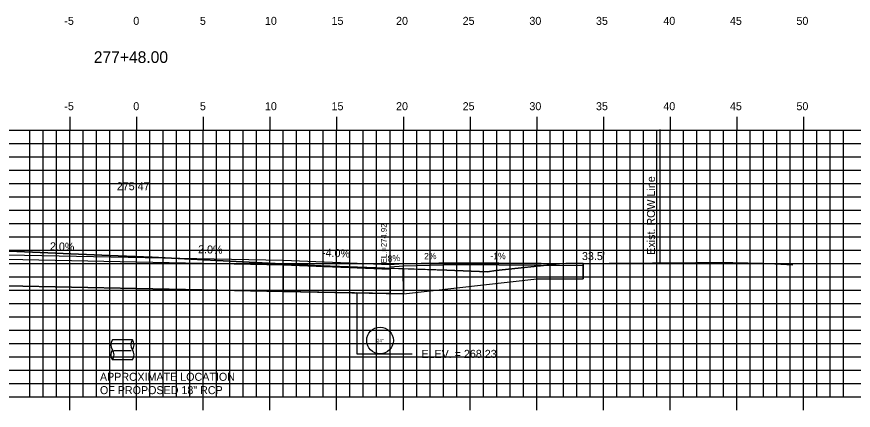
# Model space of a CAD drawing. Extents: x 854231 to 854401, y 366268 to 366378.
# Drawn here: x 854304.8 to 854367.5, y 366306.2 to 366335.7 of the extents above; entities that cross this region are included whole.
import ezdxf

# ---------------------------------------------------------------- set-up
doc = ezdxf.new("R2010")
doc.units = 0
for name, color, linetype in [('ANNOTATION', 7, 'Continuous'), ('D_Drainage_Culvert', 7, 'Continuous'), ('D_Drainage_Text', 7, 'Continuous'), ('D_Roadway_Centerline_Text', 7, 'Continuous'), ('D_Roadway_Drive_Gravel_RT', 7, 'Continuous'), ('D_Roadway_Drive_SubGrade', 7, 'Continuous'), ('D_Roadway_Edge_TW', 7, 'Continuous'), ('D_Roadway_SubGrade', 7, 'Continuous'), ('D_Text_Standard', 7, 'Continuous'), ('E_ROW_Line', 7, 'Continuous'), ('H_V ANNOTATION', 7, 'Continuous'), ('JUNK COM EXC', 7, 'Continuous'), ('junk strct exc', 7, 'Continuous'), ('MAJOR', 7, 'Continuous'), ('MINOR', 7, 'Continuous'), ('PDRAIN', 7, 'Continuous'), ('S_Roadway_Centerline', 7, 'Continuous')]:
    doc.layers.add(name, color=color, linetype=linetype)

msp = doc.modelspace()

# ---------------------------------------------------------------- linework, layer by layer
at = {"layer": 'ANNOTATION'}
msp.add_line((854312.071, 366310.722), (854313.382, 366310.722), dxfattribs=at)
at = {"layer": 'D_Drainage_Culvert'}
for p, q in [((854313.461, 366311.514), (854311.961, 366311.514)), ((854313.461, 366310.014), (854311.961, 366310.014))]:
    msp.add_line(p, q, dxfattribs=at)
for centre, start, end in [((854312.461, 366311.139), 143.1301, 216.8699), ((854313.961, 366311.139), 143.1301, 216.8699), ((854312.961, 366311.139), 323.1301, 36.8699), ((854312.461, 366310.389), 143.1301, 216.8699), ((854311.461, 366310.389), 323.1301, 36.8699), ((854312.961, 366310.389), 323.1301, 36.8699)]:
    msp.add_arc(centre, 0.625, start, end, dxfattribs=at)
at = {"layer": 'D_Roadway_Drive_Gravel_RT'}
for p, q in [((854332.77, 366317.161), (854333.77, 366317.241)), ((854332.77, 366317.161), (854333.77, 366317.241)), ((854333.77, 366317.241), (854337.77, 366317.321)), ((854337.77, 366317.321), (854347.249, 366317.248)), ((854332.771, 366316.994), (854333.778, 366317.075)), ((854332.774, 366316.828), (854332.774, 366317.162)), ((854333.778, 366317.075), (854337.773, 366317.155)), ((854337.768, 366317.155), (854347.249, 366317.081)), ((854343.771, 366316.095), (854347.249, 366316.081))]:
    msp.add_line(p, q, dxfattribs=at)
at = {"layer": 'D_Roadway_Drive_SubGrade'}
for p, q in [((854347.249, 366317.248), (854347.249, 366316.081)), ((854333.774, 366314.968), (854343.771, 366316.095)), ((854332.774, 366314.988), (854333.774, 366314.968))]:
    msp.add_line(p, q, dxfattribs=at)
at = {"layer": 'D_Roadway_Edge_TW'}
msp.add_lwpolyline([(854294.774, 366317.602), (854302.774, 366317.922), (854324.774, 366317.482), (854332.77, 366317.161)], dxfattribs=at)
at = {"layer": 'D_Roadway_SubGrade'}
for points in [[(854302.774, 366315.588), (854302.774, 366317.588), (854313.774, 366317.368), (854324.774, 366317.148), (854324.774, 366315.148), (854313.774, 366315.368)], [(854324.774, 366317.148), (854332.774, 366316.828), (854332.774, 366314.988), (854324.774, 366315.148)]]:
    msp.add_lwpolyline(points, close=True, dxfattribs=at)
at = {"layer": 'D_Text_Standard'}
msp.add_lwpolyline([(854333.774, 366310.466), (854333.763, 366310.466), (854334.443, 366310.466)], dxfattribs=at)
at = {"layer": 'E_ROW_Line'}
msp.add_line((854353.032, 366317.298), (854353.032, 366327.298), dxfattribs=at)
at = {"layer": 'JUNK COM EXC'}
for points in [[(854333.77, 366316.851), (854327.6, 366317.07), (854323.667, 366317.268), (854314.957, 366317.71), (854311.743, 366317.84), (854303.643, 366318.188), (854298.019, 366318.041), (854293.772, 366317.983), (854293.774, 366315.408), (854302.774, 366315.588), (854324.774, 366315.148), (854333.774, 366314.968), (854333.77, 366316.851)], [(854333.771, 366316.851), (854333.771, 366314.968), (854333.774, 366314.968), (854343.771, 366316.095), (854347.249, 366316.081), (854347.249, 366317.248), (854345.939, 366317.237), (854345.472, 366317.218), (854340.705, 366316.711), (854340.071, 366316.624), (854337.042, 366316.735), (854333.771, 366316.851)]]:
    msp.add_lwpolyline(points, dxfattribs=at)
at = {"layer": 'junk strct exc'}
msp.add_lwpolyline([(854330.274, 366315.038), (854330.274, 366310.466), (854333.774, 366310.466), (854333.774, 366314.97)], close=True, dxfattribs=at)
at = {"layer": 'MAJOR'}
for p, q in [((854308.771, 366328.238), (854308.771, 366327.236)), ((854313.771, 366328.238), (854313.771, 366327.236)), ((854318.771, 366328.238), (854318.771, 366327.236)), ((854323.771, 366328.238), (854323.771, 366327.236)), ((854328.771, 366328.238), (854328.771, 366327.236)), ((854333.771, 366328.238), (854333.771, 366327.236)), ((854338.771, 366328.238), (854338.771, 366327.236)), ((854343.771, 366328.238), (854343.771, 366327.236)), ((854348.771, 366328.238), (854348.771, 366327.236)), ((854353.771, 366328.238), (854353.771, 366327.236)), ((854358.771, 366328.238), (854358.771, 366327.236)), ((854363.771, 366328.238), (854363.771, 366327.236)), ((854243.771, 366327.236), (854383.771, 366327.236)), ((854243.771, 366327.236), (854383.771, 366327.236)), ((854308.771, 366307.236), (854308.771, 366327.236)), ((854313.771, 366307.236), (854313.771, 366327.236)), ((854318.771, 366307.236), (854318.771, 366327.236)), ((854323.771, 366307.236), (854323.771, 366327.236)), ((854328.771, 366307.236), (854328.771, 366327.236)), ((854333.771, 366307.236), (854333.771, 366327.236)), ((854338.771, 366307.236), (854338.771, 366327.236)), ((854343.771, 366307.236), (854343.771, 366327.236)), ((854348.771, 366307.236), (854348.771, 366327.236)), ((854353.771, 366307.236), (854353.771, 366327.236)), ((854358.771, 366307.236), (854358.771, 366327.236)), ((854363.771, 366307.236), (854363.771, 366327.236)), ((854243.771, 366322.236), (854383.771, 366322.236)), ((854243.771, 366317.236), (854383.771, 366317.236)), ((854243.771, 366312.236), (854383.771, 366312.236)), ((854243.771, 366307.236), (854383.771, 366307.236)), ((854243.771, 366307.236), (854383.771, 366307.236)), ((854308.771, 366306.234), (854308.771, 366307.236)), ((854313.771, 366306.234), (854313.771, 366307.236)), ((854318.771, 366306.234), (854318.771, 366307.236)), ((854323.771, 366306.234), (854323.771, 366307.236)), ((854328.771, 366306.234), (854328.771, 366307.236)), ((854333.771, 366306.234), (854333.771, 366307.236)), ((854338.771, 366306.234), (854338.771, 366307.236)), ((854343.771, 366306.234), (854343.771, 366307.236)), ((854348.771, 366306.234), (854348.771, 366307.236)), ((854353.771, 366306.234), (854353.771, 366307.236)), ((854358.771, 366306.234), (854358.771, 366307.236)), ((854363.771, 366306.234), (854363.771, 366307.236))]:
    msp.add_line(p, q, dxfattribs=at)
at = {"layer": 'MINOR'}
for p, q in [((854305.771, 366307.236), (854305.771, 366327.236)), ((854306.771, 366307.236), (854306.771, 366327.236)), ((854307.771, 366307.236), (854307.771, 366327.236)), ((854309.771, 366307.236), (854309.771, 366327.236)), ((854310.771, 366307.236), (854310.771, 366327.236)), ((854311.771, 366307.236), (854311.771, 366327.236)), ((854312.771, 366307.236), (854312.771, 366327.236)), ((854314.771, 366307.236), (854314.771, 366327.236)), ((854315.771, 366307.236), (854315.771, 366327.236)), ((854316.771, 366307.236), (854316.771, 366327.236)), ((854317.771, 366307.236), (854317.771, 366327.236)), ((854319.771, 366307.236), (854319.771, 366327.236)), ((854320.771, 366307.236), (854320.771, 366327.236)), ((854321.771, 366307.236), (854321.771, 366327.236)), ((854322.771, 366307.236), (854322.771, 366327.236)), ((854324.771, 366307.236), (854324.771, 366327.236)), ((854325.771, 366307.236), (854325.771, 366327.236)), ((854326.771, 366307.236), (854326.771, 366327.236)), ((854327.771, 366307.236), (854327.771, 366327.236)), ((854329.771, 366307.236), (854329.771, 366327.236)), ((854330.771, 366307.236), (854330.771, 366327.236)), ((854331.771, 366307.236), (854331.771, 366327.236)), ((854332.771, 366307.236), (854332.771, 366327.236)), ((854334.771, 366307.236), (854334.771, 366327.236)), ((854335.771, 366307.236), (854335.771, 366327.236)), ((854336.771, 366307.236), (854336.771, 366327.236)), ((854337.771, 366307.236), (854337.771, 366327.236)), ((854339.771, 366307.236), (854339.771, 366327.236)), ((854340.771, 366307.236), (854340.771, 366327.236)), ((854341.771, 366307.236), (854341.771, 366327.236)), ((854342.771, 366307.236), (854342.771, 366327.236)), ((854344.771, 366307.236), (854344.771, 366327.236)), ((854345.771, 366307.236), (854345.771, 366327.236)), ((854346.771, 366307.236), (854346.771, 366327.236)), ((854347.771, 366307.236), (854347.771, 366327.236)), ((854349.771, 366307.236), (854349.771, 366327.236)), ((854350.771, 366307.236), (854350.771, 366327.236)), ((854351.771, 366307.236), (854351.771, 366327.236)), ((854352.771, 366307.236), (854352.771, 366327.236)), ((854354.771, 366307.236), (854354.771, 366327.236)), ((854355.771, 366307.236), (854355.771, 366327.236)), ((854356.771, 366307.236), (854356.771, 366327.236)), ((854357.771, 366307.236), (854357.771, 366327.236)), ((854359.771, 366307.236), (854359.771, 366327.236)), ((854360.771, 366307.236), (854360.771, 366327.236)), ((854361.771, 366307.236), (854361.771, 366327.236)), ((854362.771, 366307.236), (854362.771, 366327.236)), ((854364.771, 366307.236), (854364.771, 366327.236)), ((854365.771, 366307.236), (854365.771, 366327.236)), ((854366.771, 366307.236), (854366.771, 366327.236)), ((854243.771, 366326.236), (854383.771, 366326.236)), ((854243.771, 366325.236), (854383.771, 366325.236)), ((854243.771, 366324.236), (854383.771, 366324.236)), ((854243.771, 366323.236), (854383.771, 366323.236)), ((854243.771, 366321.236), (854383.771, 366321.236)), ((854243.771, 366320.236), (854383.771, 366320.236)), ((854243.771, 366319.236), (854383.771, 366319.236)), ((854243.771, 366318.236), (854383.771, 366318.236)), ((854243.771, 366316.236), (854383.771, 366316.236)), ((854243.771, 366315.236), (854383.771, 366315.236)), ((854243.771, 366314.236), (854383.771, 366314.236)), ((854243.771, 366313.236), (854383.771, 366313.236)), ((854243.771, 366311.236), (854383.771, 366311.236)), ((854243.771, 366310.236), (854383.771, 366310.236)), ((854243.771, 366309.236), (854383.771, 366309.236)), ((854243.771, 366308.236), (854383.771, 366308.236))]:
    msp.add_line(p, q, dxfattribs=at)
at = {"layer": 'PDRAIN'}
msp.add_lwpolyline([(854330.274, 366315.038), (854330.274, 366310.466), (854333.774, 366310.466), (854333.774, 366314.968)], dxfattribs=at)
msp.add_circle((854332.024, 366311.466), 1, dxfattribs=at)
at = {"layer": 'S_Roadway_Centerline'}
msp.add_lwpolyline([(854303.643, 366318.188), (854311.743, 366317.84), (854314.957, 366317.71), (854323.667, 366317.268), (854327.6, 366317.07), (854337.042, 366316.735), (854340.071, 366316.624), (854340.705, 366316.711), (854345.472, 366317.218), (854345.939, 366317.237), (854355.684, 366317.321), (854358.462, 366317.307), (854360.704, 366317.259), (854362.971, 366317.131)], dxfattribs=at)

# ---------------------------------------------------------------- texts
at = {"layer": 'ANNOTATION'}
for s, rotation, p in [('2.0%', 358.85423, (854307.278, 366318.232)), ('-2.0%', 358.85423, (854318.117, 366318.015)), ('-4.0%', 357.70946, (854327.669, 366317.767))]:
    msp.add_text(s, height=0.6, rotation=rotation, dxfattribs=at).set_placement(p)
at = {"layer": 'D_Drainage_Text'}
for s, p in [('APPROXIMATE LOCATION', (854311.031, 366308.445)), ('OF PROPOSED 18" RCP', (854311.031, 366307.445))]:
    msp.add_text(s, height=0.6, dxfattribs=at).set_placement(p)
at = {"layer": 'D_Roadway_Centerline_Text'}
msp.add_text('275.47', height=0.6, dxfattribs=at).set_placement((854312.294, 366322.734))
at = {"layer": 'D_Roadway_Drive_Gravel_RT'}
for s, rotation, p in [('8%', 4.57392, (854332.617, 366317.355)), ('8%', 4.57392, (854332.617, 366317.355)), ('2%', 1.19222, (854335.332, 366317.55))]:
    msp.add_text(s, height=0.48, rotation=rotation, dxfattribs=at).set_placement(p)
msp.add_text('-1%', height=0.48, dxfattribs=at).set_placement((854340.299, 366317.561))
at = {"layer": 'D_Text_Standard'}
msp.add_text(' EL.=274.92', height=0.4335, rotation=90, dxfattribs=at).set_placement((854332.529, 366317.093))
for s, p in [("33.5'", (854347.16, 366317.498)), ('ELEV. = 268.23', (854335.123, 366310.166))]:
    msp.add_text(s, height=0.6, dxfattribs=at).set_placement(p)
at = {"layer": 'E_ROW_Line'}
msp.add_text('Exist. ROW Line', height=0.6, rotation=90, dxfattribs=at).set_placement((854352.632, 366317.898))
at = {"layer": 'H_V ANNOTATION'}
for s, height, p in [('-5', 0.6, (854308.361, 366335.136)), ('0', 0.6, (854313.53, 366335.136)), ('5', 0.6, (854318.522, 366335.136)), ('10', 0.6, (854323.396, 366335.136)), ('15', 0.6, (854328.388, 366335.136)), ('20', 0.6, (854333.225, 366335.136)), ('25', 0.6, (854338.217, 366335.136)), ('30', 0.6, (854343.219, 366335.136)), ('35', 0.6, (854348.211, 366335.136)), ('40', 0.6, (854353.257, 366335.136)), ('45', 0.6, (854358.249, 366335.136)), ('50', 0.6, (854363.235, 366335.136)), ('277+48.00', 0.875, (854310.571, 366332.28)), ('-5', 0.6, (854308.361, 366328.736)), ('0', 0.6, (854313.53, 366328.736)), ('5', 0.6, (854318.522, 366328.736)), ('10', 0.6, (854323.396, 366328.736)), ('15', 0.6, (854328.388, 366328.736)), ('20', 0.6, (854333.225, 366328.736)), ('25', 0.6, (854338.217, 366328.736)), ('30', 0.6, (854343.219, 366328.736)), ('35', 0.6, (854348.211, 366328.736)), ('40', 0.6, (854353.257, 366328.736)), ('45', 0.6, (854358.249, 366328.736)), ('50', 0.6, (854363.235, 366328.736))]:
    msp.add_text(s, height=height, dxfattribs=at).set_placement(p)
at = {"layer": 'PDRAIN'}
msp.add_text('24"', height=0.25, dxfattribs=at).set_placement((854331.782, 366311.341))
at = {"layer": 'S_Roadway_Centerline'}
for s, p in [('C', (854314.952, 366317.71)), ('L', (854314.957, 366317.703))]:
    msp.add_text(s, height=0.0146, dxfattribs=at).set_placement(p)

doc.saveas('drawing.dxf')
